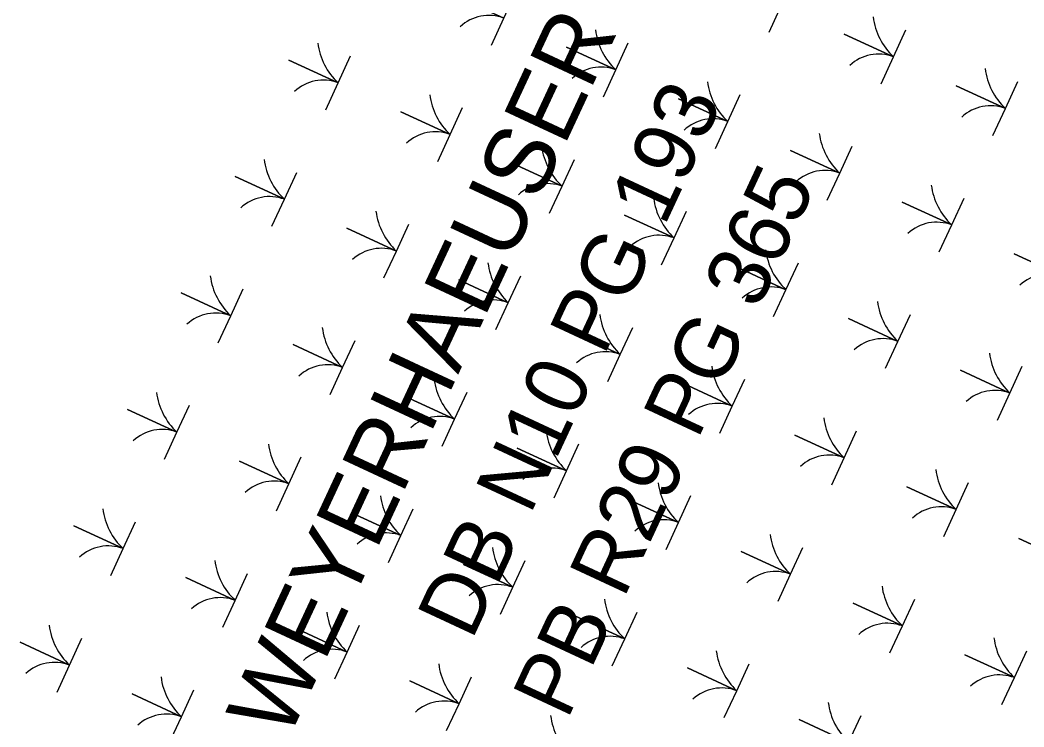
# Model space of a CAD drawing. Extents: x 2532037 to 2533565, y 713396 to 716867.
# Drawn here: x 2532613.5 to 2532686.3, y 715588.4 to 715639.7 of the extents above; entities that cross this region are included whole.
import ezdxf

# ---------------------------------------------------------------- set-up
doc = ezdxf.new("R2010")
doc.units = 0
for name, color, linetype in [('Exist Property Deed Book Text', 7, 'Continuous'), ('Exist Property Owner Text', 7, 'Continuous'), ('Scratch_Level_1', 7, 'Continuous')]:
    doc.layers.add(name, color=color, linetype=linetype)

msp = doc.modelspace()

# ---------------------------------------------------------------- linework, layer by layer
at = {"layer": 'Scratch_Level_1'}
for points in [[(2532667.792, 715638.844), (2532668.693, 715640.796), (2532665.111, 715642.45), (2532668.693, 715640.796), (2532669.595, 715642.749)], [(2532647.651, 715637.898), (2532648.552, 715639.851), (2532644.97, 715641.504), (2532648.552, 715639.851), (2532649.453, 715641.803)], [(2532675.913, 715635.094), (2532676.815, 715637.047), (2532673.233, 715638.7), (2532676.815, 715637.047), (2532677.716, 715638.999)], [(2532655.772, 715634.149), (2532656.673, 715636.101), (2532653.091, 715637.755), (2532656.673, 715636.101), (2532657.575, 715638.054)], [(2532635.631, 715633.203), (2532636.532, 715635.156), (2532632.95, 715636.809), (2532636.532, 715635.156), (2532637.433, 715637.108)], [(2532684.035, 715631.345), (2532684.936, 715633.297), (2532681.354, 715634.951), (2532684.936, 715633.297), (2532685.837, 715635.25)], [(2532663.893, 715630.399), (2532664.795, 715632.352), (2532661.213, 715634.005), (2532664.795, 715632.352), (2532665.696, 715634.304)], [(2532643.752, 715629.454), (2532644.653, 715631.406), (2532641.072, 715633.06), (2532644.653, 715631.406), (2532645.555, 715633.359)], [(2532672.015, 715626.65), (2532672.916, 715628.602), (2532669.334, 715630.256), (2532672.916, 715628.602), (2532673.818, 715630.555)], [(2532651.874, 715625.704), (2532652.775, 715627.657), (2532649.193, 715629.31), (2532652.775, 715627.657), (2532653.676, 715629.609)], [(2532631.732, 715624.759), (2532632.634, 715626.711), (2532629.052, 715628.365), (2532632.634, 715626.711), (2532633.535, 715628.664)], [(2532680.136, 715622.901), (2532681.038, 715624.853), (2532677.456, 715626.507), (2532681.038, 715624.853), (2532681.939, 715626.805)], [(2532659.995, 715621.955), (2532660.896, 715623.907), (2532657.314, 715625.561), (2532660.896, 715623.907), (2532661.798, 715625.86)], [(2532639.854, 715621.009), (2532640.755, 715622.962), (2532637.173, 715624.615), (2532640.755, 715622.962), (2532641.656, 715624.914)], [(2532688.258, 715619.151), (2532689.159, 715621.104), (2532685.577, 715622.757), (2532689.159, 715621.104), (2532690.06, 715623.056)], [(2532668.116, 715618.206), (2532669.018, 715620.158), (2532665.436, 715621.812), (2532669.018, 715620.158), (2532669.919, 715622.111)], [(2532647.975, 715617.26), (2532648.876, 715619.212), (2532645.295, 715620.866), (2532648.876, 715619.212), (2532649.778, 715621.165)], [(2532627.834, 715616.314), (2532628.735, 715618.267), (2532625.153, 715619.92), (2532628.735, 715618.267), (2532629.636, 715620.219)], [(2532676.238, 715614.456), (2532677.139, 715616.409), (2532673.557, 715618.062), (2532677.139, 715616.409), (2532678.041, 715618.361)], [(2532656.096, 715613.511), (2532656.998, 715615.463), (2532653.416, 715617.117), (2532656.998, 715615.463), (2532657.899, 715617.416)], [(2532635.955, 715612.565), (2532636.857, 715614.517), (2532633.275, 715616.171), (2532636.857, 715614.517), (2532637.758, 715616.47)], [(2532684.359, 715610.707), (2532685.261, 715612.659), (2532681.679, 715614.313), (2532685.261, 715612.659), (2532686.162, 715614.612)], [(2532664.218, 715609.761), (2532665.119, 715611.714), (2532661.537, 715613.367), (2532665.119, 715611.714), (2532666.021, 715613.666)], [(2532644.077, 715608.816), (2532644.978, 715610.768), (2532641.396, 715612.422), (2532644.978, 715610.768), (2532645.879, 715612.721)], [(2532623.935, 715607.87), (2532624.837, 715609.823), (2532621.255, 715611.476), (2532624.837, 715609.823), (2532625.738, 715611.775)], [(2532672.339, 715606.012), (2532673.241, 715607.964), (2532669.659, 715609.618), (2532673.241, 715607.964), (2532674.142, 715609.917)], [(2532652.198, 715605.066), (2532653.099, 715607.019), (2532649.518, 715608.672), (2532653.099, 715607.019), (2532654.001, 715608.971)], [(2532632.057, 715604.121), (2532632.958, 715606.073), (2532629.376, 715607.727), (2532632.958, 715606.073), (2532633.859, 715608.026)], [(2532680.461, 715602.263), (2532681.362, 715604.215), (2532677.78, 715605.869), (2532681.362, 715604.215), (2532682.264, 715606.167)], [(2532660.319, 715601.317), (2532661.221, 715603.269), (2532657.639, 715604.923), (2532661.221, 715603.269), (2532662.122, 715605.222)], [(2532640.178, 715600.371), (2532641.079, 715602.324), (2532637.498, 715603.977), (2532641.079, 715602.324), (2532641.981, 715604.276)], [(2532620.037, 715599.426), (2532620.938, 715601.378), (2532617.356, 715603.032), (2532620.938, 715601.378), (2532621.84, 715603.331)], [(2532688.582, 715598.513), (2532689.484, 715600.466), (2532685.902, 715602.119), (2532689.484, 715600.466), (2532690.385, 715602.418)], [(2532668.441, 715597.568), (2532669.342, 715599.52), (2532665.76, 715601.174), (2532669.342, 715599.52), (2532670.244, 715601.472)], [(2532648.3, 715596.622), (2532649.201, 715598.574), (2532645.619, 715600.228), (2532649.201, 715598.574), (2532650.102, 715600.527)], [(2532628.158, 715595.676), (2532629.06, 715597.629), (2532625.478, 715599.282), (2532629.06, 715597.629), (2532629.961, 715599.581)], [(2532676.562, 715593.818), (2532677.464, 715595.771), (2532673.882, 715597.424), (2532677.464, 715595.771), (2532678.365, 715597.723)], [(2532656.421, 715592.873), (2532657.322, 715594.825), (2532653.741, 715596.479), (2532657.322, 715594.825), (2532658.224, 715596.777)], [(2532636.28, 715591.927), (2532637.181, 715593.879), (2532633.599, 715595.533), (2532637.181, 715593.879), (2532638.082, 715595.832)], [(2532616.138, 715590.981), (2532617.04, 715592.934), (2532613.458, 715594.587), (2532617.04, 715592.934), (2532617.941, 715594.886)], [(2532684.684, 715590.069), (2532685.585, 715592.021), (2532682.003, 715593.675), (2532685.585, 715592.021), (2532686.486, 715593.974)], [(2532664.542, 715589.123), (2532665.444, 715591.076), (2532661.862, 715592.729), (2532665.444, 715591.076), (2532666.345, 715593.028)], [(2532644.401, 715588.178), (2532645.302, 715590.13), (2532641.721, 715591.784), (2532645.302, 715590.13), (2532646.204, 715592.082)], [(2532624.26, 715587.232), (2532625.161, 715589.184), (2532621.579, 715590.838), (2532625.161, 715589.184), (2532626.063, 715591.137)], [(2532672.664, 715585.374), (2532673.565, 715587.326), (2532669.983, 715588.98), (2532673.565, 715587.326), (2532674.467, 715589.279)]]:
    msp.add_lwpolyline(points, dxfattribs=at)
for centre, radius, start, end in [((2532647.468, 715636.973), 3.075, 69.35932, 132.75394), ((2532680.102, 715640.552), 4.806, 187.34643, 226.84116), ((2532659.96, 715639.607), 4.806, 187.34643, 226.84116), ((2532639.819, 715638.661), 4.806, 187.34643, 226.84116), ((2532675.731, 715634.17), 3.075, 69.35932, 132.75394), ((2532655.589, 715633.224), 3.075, 69.35932, 132.75394), ((2532688.223, 715636.803), 4.806, 187.34643, 226.84116), ((2532635.448, 715632.278), 3.075, 69.35932, 132.75394), ((2532668.082, 715635.857), 4.806, 187.34643, 226.84116), ((2532647.941, 715634.912), 4.806, 187.34643, 226.84116), ((2532683.852, 715630.42), 3.075, 69.35932, 132.75394), ((2532663.711, 715629.475), 3.075, 69.35932, 132.75394), ((2532643.57, 715628.529), 3.075, 69.35932, 132.75394), ((2532676.203, 715632.108), 4.806, 187.34643, 226.84116), ((2532656.062, 715631.162), 4.806, 187.34643, 226.84116), ((2532635.921, 715630.217), 4.806, 187.34643, 226.84116), ((2532671.832, 715625.725), 3.075, 69.35932, 132.75394), ((2532651.691, 715624.78), 3.075, 69.35932, 132.75394), ((2532684.325, 715628.359), 4.806, 187.34643, 226.84116), ((2532631.55, 715623.834), 3.075, 69.35932, 132.75394), ((2532664.183, 715627.413), 4.806, 187.34643, 226.84116), ((2532644.042, 715626.467), 4.806, 187.34643, 226.84116), ((2532679.954, 715621.976), 3.075, 69.35932, 132.75394), ((2532659.812, 715621.03), 3.075, 69.35932, 132.75394), ((2532639.671, 715620.085), 3.075, 69.35932, 132.75394), ((2532672.305, 715623.664), 4.806, 187.34643, 226.84116), ((2532652.164, 715622.718), 4.806, 187.34643, 226.84116), ((2532632.022, 715621.772), 4.806, 187.34643, 226.84116), ((2532688.075, 715618.226), 3.075, 69.35932, 132.75394), ((2532667.934, 715617.281), 3.075, 69.35932, 132.75394), ((2532647.793, 715616.335), 3.075, 69.35932, 132.75394), ((2532680.426, 715619.914), 4.806, 187.34643, 226.84116), ((2532627.651, 715615.39), 3.075, 69.35932, 132.75394), ((2532660.285, 715618.969), 4.806, 187.34643, 226.84116), ((2532640.144, 715618.023), 4.806, 187.34643, 226.84116), ((2532676.055, 715613.532), 3.075, 69.35932, 132.75394), ((2532655.914, 715612.586), 3.075, 69.35932, 132.75394), ((2532688.548, 715616.165), 4.806, 187.34643, 226.84116), ((2532635.773, 715611.64), 3.075, 69.35932, 132.75394), ((2532668.406, 715615.219), 4.806, 187.34643, 226.84116), ((2532648.265, 715614.274), 4.806, 187.34643, 226.84116), ((2532628.124, 715613.328), 4.806, 187.34643, 226.84116), ((2532684.177, 715609.782), 3.075, 69.35932, 132.75394), ((2532664.035, 715608.837), 3.075, 69.35932, 132.75394), ((2532643.894, 715607.891), 3.075, 69.35932, 132.75394), ((2532676.528, 715611.47), 4.806, 187.34643, 226.84116), ((2532623.753, 715606.945), 3.075, 69.35932, 132.75394), ((2532656.387, 715610.524), 4.806, 187.34643, 226.84116), ((2532636.245, 715609.579), 4.806, 187.34643, 226.84116), ((2532672.157, 715605.087), 3.075, 69.35932, 132.75394), ((2532652.016, 715604.142), 3.075, 69.35932, 132.75394), ((2532684.649, 715607.721), 4.806, 187.34643, 226.84116), ((2532631.874, 715603.196), 3.075, 69.35932, 132.75394), ((2532664.508, 715606.775), 4.806, 187.34643, 226.84116), ((2532644.367, 715605.829), 4.806, 187.34643, 226.84116), ((2532624.225, 715604.884), 4.806, 187.34643, 226.84116), ((2532680.278, 715601.338), 3.075, 69.35932, 132.75394), ((2532660.137, 715600.392), 3.075, 69.35932, 132.75394), ((2532639.996, 715599.447), 3.075, 69.35932, 132.75394), ((2532672.629, 715603.026), 4.806, 187.34643, 226.84116), ((2532619.854, 715598.501), 3.075, 69.35932, 132.75394), ((2532652.488, 715602.08), 4.806, 187.34643, 226.84116), ((2532632.347, 715601.134), 4.806, 187.34643, 226.84116), ((2532668.258, 715596.643), 3.075, 69.35932, 132.75394), ((2532648.117, 715595.697), 3.075, 69.35932, 132.75394), ((2532680.751, 715599.276), 4.806, 187.34643, 226.84116), ((2532627.976, 715594.752), 3.075, 69.35932, 132.75394), ((2532660.61, 715598.331), 4.806, 187.34643, 226.84116), ((2532640.468, 715597.385), 4.806, 187.34643, 226.84116), ((2532620.327, 715596.439), 4.806, 187.34643, 226.84116), ((2532676.38, 715592.893), 3.075, 69.35932, 132.75394), ((2532656.239, 715591.948), 3.075, 69.35932, 132.75394), ((2532688.872, 715595.527), 4.806, 187.34643, 226.84116), ((2532636.097, 715591.002), 3.075, 69.35932, 132.75394), ((2532668.731, 715594.581), 4.806, 187.34643, 226.84116), ((2532615.956, 715590.057), 3.075, 69.35932, 132.75394), ((2532648.59, 715593.636), 4.806, 187.34643, 226.84116), ((2532628.448, 715592.69), 4.806, 187.34643, 226.84116), ((2532684.501, 715589.144), 3.075, 69.35932, 132.75394), ((2532664.36, 715588.198), 3.075, 69.35932, 132.75394), ((2532644.219, 715587.253), 3.075, 69.35932, 132.75394), ((2532676.852, 715590.832), 4.806, 187.34643, 226.84116), ((2532624.077, 715586.307), 3.075, 69.35932, 132.75394), ((2532656.711, 715589.886), 4.806, 187.34643, 226.84116)]:
    msp.add_arc(centre, radius, start, end, dxfattribs=at)

# ---------------------------------------------------------------- texts
at = {"layer": 'Exist Property Deed Book Text'}
for s, p in [('DB N10 PG 193', (2532646.221, 715594.66)), ('PB R29 PG 365', (2532653.149, 715588.896))]:
    msp.add_text(s, height=4.5, rotation=65.05, dxfattribs=at).set_placement(p)
at = {"layer": 'Exist Property Owner Text'}
msp.add_text('WEYERHAEUSER CO', height=5, rotation=65.05, dxfattribs=at).set_placement((2532632.854, 715587.369))

doc.saveas('drawing.dxf')
